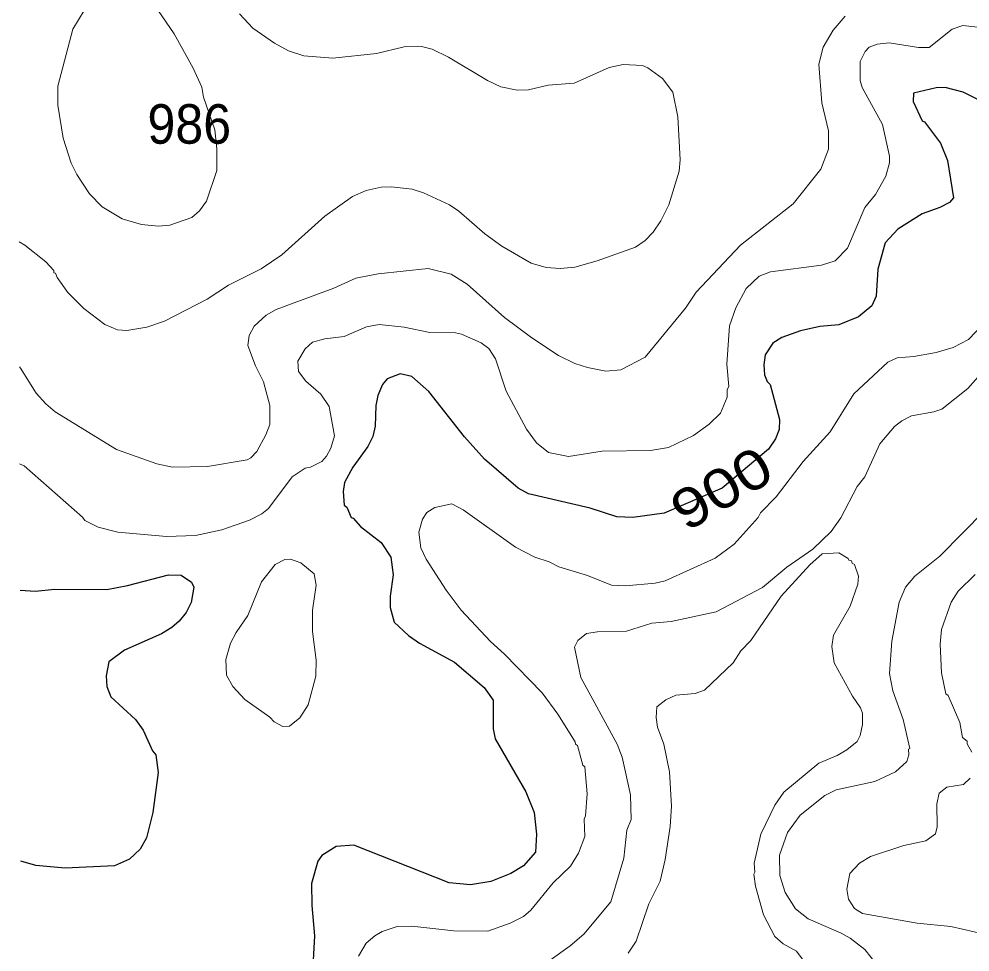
# Model space of a CAD drawing. Extents: x 447.8 to 473.9, y 7733.1 to 7760.8.
# Drawn here: x 447.836 to 449.762, y 7740.259 to 7742.149 of the extents above; entities that cross this region are included whole.
import ezdxf
from ezdxf.enums import TextEntityAlignment as Align

# ---------------------------------------------------------------- set-up
doc = ezdxf.new("R2010")
doc.units = 0
doc.header["$LTSCALE"] = 0.032
doc.layers.add('1', color=7, linetype='Continuous', lineweight=25)
doc.layers.add('2', color=7, linetype='Continuous', lineweight=13)
doc.layers.add('21', color=7, linetype='Continuous')
doc.layers.add('61', color=7, linetype='Continuous')

msp = doc.modelspace()

# ---------------------------------------------------------------- linework, layer by layer
at = {"layer": '1'}
for points in [[(449.7846, 7741.9822), (449.748, 7742.0006), (449.7116, 7742.0101), (449.6935, 7742.0093), (449.6478, 7741.9983), (449.6471, 7741.9817), (449.6649, 7741.9422), (449.6696, 7741.9401), (449.7019, 7741.8969), (449.7162, 7741.8619), (449.7287, 7741.7866), (449.7201, 7741.7772), (449.7008, 7741.7668), (449.6651, 7741.7538), (449.6156, 7741.7229), (449.5901, 7741.6954), (449.5753, 7741.6422), (449.5717, 7741.587), (449.5631, 7741.5673), (449.536, 7741.5454), (449.4961, 7741.5291), (449.4576, 7741.5259), (449.4187, 7741.5169), (449.3809, 7741.5035), (449.3626, 7741.4923), (449.3472, 7741.4686), (449.3442, 7741.4482), (449.3457, 7741.4277), (449.3513, 7741.4142), (449.3572, 7741.4082), (449.3761, 7741.3372), (449.3752, 7741.3172), (449.3681, 7741.2984), (449.354, 7741.2771), (449.2597, 7741.1986), (449.1422, 7741.1474), (449.079, 7741.139), (449.0463, 7741.1404), (448.9927, 7741.1581), (448.8676, 7741.1871), (448.8464, 7741.1985), (448.7784, 7741.2572), (448.7383, 7741.3025), (448.6657, 7741.3938), (448.6311, 7741.4242), (448.6079, 7741.4296), (448.5816, 7741.4199), (448.572, 7741.4086), (448.5624, 7741.3859), (448.5586, 7741.3659), (448.5569, 7741.3239), (448.552, 7741.3029), (448.5419, 7741.2826), (448.5119, 7741.2411), (448.4946, 7741.2095), (448.4921, 7741.1913), (448.4945, 7741.164), (448.4993, 7741.1601), (448.5085, 7741.1387), (448.5122, 7741.1377), (448.5276, 7741.1204), (448.5689, 7741.0883), (448.589, 7741.0586), (448.5938, 7741.0226), (448.5874, 7740.9797), (448.5874, 7740.9565), (448.5954, 7740.9269), (448.6245, 7740.8997), (448.6468, 7740.8842), (448.7179, 7740.8457), (448.7781, 7740.7949), (448.7961, 7740.7692), (448.7959, 7740.7112), (448.7999, 7740.6908), (448.8623, 7740.5835), (448.8792, 7740.5413), (448.8839, 7740.4976), (448.882, 7740.461), (448.8578, 7740.4337), (448.8319, 7740.4177), (448.7914, 7740.4014), (448.7502, 7740.395), (448.7068, 7740.3992), (448.5136, 7740.4751), (448.478, 7740.4725), (448.449, 7740.4544), (448.4412, 7740.4429), (448.4279, 7740.3973), (448.4287, 7740.3532), (448.4342, 7740.2919)], [(447.8377, 7740.9914), (447.8684, 7740.9898), (447.9084, 7740.9937), (448.0138, 7740.993), (448.0555, 7741.001), (448.1385, 7741.0225), (448.1641, 7741.0224), (448.185, 7741.0081), (448.1899, 7740.9979), (448.1842, 7740.9665), (448.1739, 7740.9468), (448.1603, 7740.9291), (448.1452, 7740.9162), (448.124, 7740.9035), (448.0496, 7740.8702), (448.0177, 7740.8463), (448.0119, 7740.8182), (448.0134, 7740.7969), (448.0215, 7740.776), (448.0717, 7740.7295), (448.0874, 7740.708), (448.1059, 7740.6665), (448.1124, 7740.6581), (448.1175, 7740.6226), (448.1067, 7740.5416), (448.0937, 7740.4898), (448.0813, 7740.467), (448.0596, 7740.4469), (448.0287, 7740.4335), (447.929, 7740.4288), (447.8695, 7740.4342), (447.8393, 7740.4426)], [(448.4342, 7740.2919), (448.4294, 7740.2049), (448.407, 7740.1153), (448.3948, 7740.0924), (448.3799, 7740.0722), (448.346, 7740.0451)]]:
    msp.add_lwpolyline(points, dxfattribs=at)
at = {"layer": '2'}
for points in [[(447.8356, 7741.6971), (447.8473, 7741.6907), (447.8898, 7741.6568), (447.9058, 7741.6392), (447.9063, 7741.6343), (447.9097, 7741.6335), (447.9128, 7741.625), (447.9346, 7741.5949), (447.9666, 7741.5619), (448.0097, 7741.5298), (448.0348, 7741.5188), (448.0538, 7741.518), (448.0942, 7741.5245), (448.1305, 7741.5364), (448.2167, 7741.5811), (448.2597, 7741.6098), (448.326, 7741.6429), (448.368, 7741.6712), (448.4551, 7741.7494), (448.5111, 7741.7891), (448.5386, 7741.801), (448.5694, 7741.8081), (448.5897, 7741.8089), (448.6319, 7741.8042), (448.655, 7741.7968), (448.7076, 7741.772), (448.7266, 7741.7594), (448.7792, 7741.7134), (448.8135, 7741.6882), (448.8727, 7741.6543), (448.9032, 7741.6451), (448.9315, 7741.6431), (448.9614, 7741.646), (449.0068, 7741.6588), (449.0846, 7741.6865), (449.1042, 7741.6997), (449.1202, 7741.7165), (449.1358, 7741.7395), (449.1516, 7741.7725), (449.1725, 7741.8402), (449.1748, 7741.8633), (449.1702, 7741.9502), (449.1597, 7742.0005), (449.1391, 7742.0282), (449.1094, 7742.0496), (449.0985, 7742.0543), (449.0597, 7742.0565), (449.0312, 7742.0501), (448.9598, 7742.0187), (448.9072, 7742.0149), (448.8676, 7742.0053), (448.8448, 7742.0046), (448.8115, 7742.0111), (448.7844, 7742.0241), (448.7054, 7742.0714), (448.6726, 7742.0877), (448.6506, 7742.0926), (448.6159, 7742.0919), (448.5598, 7742.079), (448.4715, 7742.0695), (448.4123, 7742.0743), (448.3815, 7742.0841), (448.3531, 7742.0993), (448.3095, 7742.13), (448.2821, 7742.1592)], [(449.5092, 7742.1544), (449.4845, 7742.1258), (449.4642, 7742.0916), (449.4556, 7742.0574), (449.4618, 7741.9791), (449.4755, 7741.9219), (449.4756, 7741.8849), (449.46, 7741.8445), (449.404, 7741.7742), (449.2971, 7741.6907), (449.2075, 7741.5955), (449.1859, 7741.5626), (449.104, 7741.4638), (449.0545, 7741.4381), (449.0244, 7741.4355), (448.9869, 7741.4426), (448.9615, 7741.4509), (448.9286, 7741.4668), (448.8746, 7741.5026), (448.819, 7741.5441), (448.7435, 7741.6113), (448.7108, 7741.6318), (448.6647, 7741.643), (448.563, 7741.6326), (448.5177, 7741.6236), (448.4732, 7741.6036), (448.3563, 7741.5603), (448.3364, 7741.5485), (448.3122, 7741.5265), (448.3015, 7741.5074), (448.299, 7741.4876), (448.3147, 7741.4461), (448.3307, 7741.414), (448.3437, 7741.3656), (448.3437, 7741.3276), (448.3356, 7741.3061), (448.3172, 7741.2727), (448.3052, 7741.2599), (448.2977, 7741.2558), (448.2177, 7741.2423), (448.1462, 7741.2407), (448.1146, 7741.2474), (448.0332, 7741.2763), (447.909, 7741.353), (447.8899, 7741.3689), (447.8704, 7741.3907), (447.8383, 7741.4416), (447.8363, 7741.4441)], [(448.1176, 7742.1656), (448.1501, 7742.1185), (448.1881, 7742.0489), (448.2056, 7742.0108), (448.2091, 7741.9906), (448.2322, 7741.9242), (448.2363, 7741.8854), (448.2364, 7741.842), (448.2157, 7741.7798), (448.2014, 7741.7603), (448.1858, 7741.7465), (448.1408, 7741.7313), (448.1184, 7741.7287), (448.0835, 7741.7325), (448.0446, 7741.7438), (448.0037, 7741.7681), (447.9784, 7741.7946), (447.9527, 7741.8336), (447.9415, 7741.8563), (447.9253, 7741.9072), (447.9141, 7741.9742), (447.9141, 7742.0128), (447.9449, 7742.1281), (447.9673, 7742.1658)], [(447.8369, 7741.2478), (447.8458, 7741.2437), (447.9645, 7741.1398), (447.969, 7741.1331), (447.9962, 7741.1192), (448.0356, 7741.1091), (448.1345, 7741.1004), (448.193, 7741.1025), (448.2465, 7741.1141), (448.3022, 7741.1336), (448.3274, 7741.1461), (448.3407, 7741.157), (448.3892, 7741.2216), (448.4155, 7741.2387), (448.4259, 7741.2409), (448.4487, 7741.2523), (448.4585, 7741.2631), (448.4671, 7741.279), (448.4748, 7741.3042), (448.4639, 7741.3635), (448.4472, 7741.3886), (448.4169, 7741.415), (448.4014, 7741.4348), (448.4001, 7741.4558), (448.4155, 7741.4807), (448.4303, 7741.4938), (448.4551, 7741.5009), (448.4943, 7741.5052), (448.5397, 7741.5254), (448.5652, 7741.5298), (448.6161, 7741.5243), (448.6675, 7741.5139), (448.7198, 7741.5129), (448.7322, 7741.5104), (448.772, 7741.493), (448.7874, 7741.4811), (448.8006, 7741.46), (448.8227, 7741.3951), (448.8638, 7741.3177), (448.8841, 7741.2902), (448.908, 7741.2705), (448.9485, 7741.2622), (449.0169, 7741.2734), (449.1145, 7741.2743), (449.1513, 7741.2807), (449.2016, 7741.3049), (449.2336, 7741.3281), (449.2563, 7741.3501), (449.27, 7741.3829), (449.2703, 7741.3981), (449.2734, 7741.4043), (449.2696, 7741.4492), (449.2751, 7741.5271), (449.2876, 7741.5637), (449.3086, 7741.6025), (449.3351, 7741.6277), (449.3578, 7741.6363), (449.4609, 7741.6502), (449.4888, 7741.6589), (449.5137, 7741.6845), (449.5487, 7741.7667), (449.5708, 7741.7928), (449.5915, 7741.8302), (449.5988, 7741.857), (449.5989, 7741.871), (449.585, 7741.935), (449.5437, 7742.01), (449.5397, 7742.0238), (449.5397, 7742.0622), (449.5494, 7742.0826), (449.5579, 7742.0912), (449.5738, 7742.0973), (449.5979, 7742.1005), (449.6573, 7742.0906), (449.6792, 7742.0911), (449.7255, 7742.1277), (449.7471, 7742.1356), (449.7839, 7742.1313)], [(449.7879, 7741.5297), (449.7592, 7741.4997), (449.7279, 7741.483), (449.6932, 7741.473), (449.6484, 7741.465), (449.6147, 7741.4625), (449.5952, 7741.4532), (449.5263, 7741.3897), (449.479, 7741.3121), (449.424, 7741.2524), (449.3694, 7741.1811), (449.3373, 7741.1481), (449.3327, 7741.1389), (449.2839, 7741.0852), (449.2457, 7741.0567), (449.1443, 7741.0108)], [(449.804, 7741.4528), (449.7575, 7741.3999), (449.7048, 7741.3585), (449.6884, 7741.3528), (449.6437, 7741.3447), (449.6236, 7741.3348), (449.6092, 7741.3229), (449.5794, 7741.2881), (449.5486, 7741.2216), (449.5332, 7741.2015), (449.5006, 7741.1383), (449.4807, 7741.1108), (449.4438, 7741.0749)], [(448.9293, 7741.0391), (448.9096, 7741.049), (448.8805, 7741.0588), (448.841, 7741.0786), (448.7355, 7741.1545), (448.7126, 7741.1667), (448.6782, 7741.1592), (448.6616, 7741.1487), (448.6532, 7741.1355), (448.6452, 7741.1094), (448.6492, 7741.0772), (448.66, 7741.0546), (448.7011, 7740.9916), (448.7312, 7740.951), (448.7905, 7740.8876), (448.819, 7740.8622), (448.8954, 7740.7835), (448.9272, 7740.7404), (448.9624, 7740.6842), (448.9629, 7740.6795), (448.9672, 7740.6768), (448.9778, 7740.6375), (448.9817, 7740.6336), (448.9866, 7740.5793), (448.9833, 7740.5345), (448.9801, 7740.5277), (448.9817, 7740.493), (448.9692, 7740.4588), (448.9527, 7740.4324), (448.9174, 7740.3987), (448.8725, 7740.3434), (448.8577, 7740.3305), (448.8304, 7740.317), (448.7855, 7740.3012), (448.7161, 7740.302), (448.6313, 7740.3115), (448.6018, 7740.3107), (448.5711, 7740.3006), (448.5563, 7740.2919), (448.5391, 7740.2769), (448.5234, 7740.2501)], [(449.5747, 7740.2317), (449.5488, 7740.2639), (449.5195, 7740.2866), (449.5009, 7740.2973), (449.4341, 7740.3259), (449.4083, 7740.3461), (449.3875, 7740.3795), (449.3769, 7740.4137), (449.3762, 7740.455), (449.3925, 7740.5006), (449.4176, 7740.5357), (449.4681, 7740.5757), (449.4906, 7740.5875), (449.5692, 7740.6044), (449.6108, 7740.6236), (449.634, 7740.6449), (449.6382, 7740.6582), (449.6376, 7740.6698), (449.6398, 7740.6711), (449.6266, 7740.7297), (449.6053, 7740.7876), (449.599, 7740.823), (449.6039, 7740.8883), (449.6185, 7740.9671), (449.6313, 7740.9976), (449.6503, 7741.0201), (449.7011, 7741.0605), (449.7919, 7741.153)], [(449.0696, 7740.2568), (449.086, 7740.281), (449.1114, 7740.3566), (449.1341, 7740.4025), (449.1444, 7740.4463), (449.1549, 7740.5131), (449.1573, 7740.5544), (449.1533, 7740.6238), (449.142, 7740.6795), (449.129, 7740.7143), (449.1261, 7740.7337), (449.1279, 7740.7551), (449.1459, 7740.7694), (449.1661, 7740.7789), (449.2053, 7740.7823), (449.2238, 7740.7894), (449.2819, 7740.8448), (449.2979, 7740.8689), (449.3178, 7740.8898), (449.3796, 7740.9796), (449.4376, 7741.0432), (449.4627, 7741.0656), (449.4961, 7741.0674), (449.5151, 7741.0558), (449.5166, 7741.0524), (449.5219, 7741.0513), (449.5235, 7741.0462), (449.5283, 7741.0439), (449.5364, 7741.0201), (449.5349, 7741.0037), (449.5191, 7740.9591), (449.4851, 7740.9004), (449.482, 7740.8776), (449.4869, 7740.8444), (449.5238, 7740.777), (449.5404, 7740.7532), (449.5442, 7740.7427), (449.5444, 7740.7196), (449.5396, 7740.6974), (449.5331, 7740.6854), (449.5127, 7740.6684), (449.4928, 7740.6569), (449.4558, 7740.6414), (449.3845, 7740.5828), (449.3666, 7740.556), (449.338, 7740.4978), (449.3249, 7740.4387), (449.3263, 7740.4208), (449.3241, 7740.4164), (449.3277, 7740.3925), (449.3438, 7740.3339), (449.3664, 7740.2903), (449.3833, 7740.2756), (449.4104, 7740.2605), (449.4322, 7740.2316)], [(449.4438, 7741.0749), (449.3911, 7741.0383), (449.3414, 7740.997), (449.2475, 7740.9478), (449.1569, 7740.9281), (449.1173, 7740.9247)], [(449.1443, 7741.0108), (449.1241, 7741.0057), (449.0641, 7741.0002), (449.0359, 7741.0018), (448.9872, 7741.0213), (448.9293, 7741.0391)], [(449.7657, 7740.6639), (449.7563, 7740.6804), (449.7559, 7740.6861), (449.7464, 7740.6935), (449.7413, 7740.7234), (449.7177, 7740.7785), (449.7129, 7740.7817), (449.7041, 7740.8242), (449.7016, 7740.8823), (449.7041, 7740.9123), (449.7239, 7740.9677), (449.7377, 7740.9895), (449.7722, 7741.0237)], [(449.1173, 7740.9247), (449.0664, 7740.9087), (449.0071, 7740.9071), (448.9848, 7740.904), (448.9678, 7740.89), (448.961, 7740.8764), (448.9735, 7740.8148), (449.0475, 7740.6795), (449.0572, 7740.6535), (449.0739, 7740.5769), (449.0754, 7740.5272), (449.0669, 7740.5054), (449.0604, 7740.449), (449.0346, 7740.3605), (448.9799, 7740.2953), (448.9519, 7740.2713), (448.8754, 7740.2164)], [(449.692, 7740.4981), (449.6951, 7740.5124), (449.6947, 7740.559), (449.6998, 7740.5804), (449.7148, 7740.5929), (449.7489, 7740.5979), (449.762, 7740.6112)], [(449.5188, 7740.4178), (449.5378, 7740.4388), (449.5602, 7740.4525), (449.6278, 7740.4743), (449.6725, 7740.484), (449.692, 7740.4981)], [(449.903, 7740.2462), (449.8247, 7740.2915), (449.794, 7740.2945), (449.7231, 7740.3106), (449.6551, 7740.3172), (449.544, 7740.337), (449.5277, 7740.347), (449.5157, 7740.3657), (449.5125, 7740.3861), (449.5188, 7740.4178)]]:
    msp.add_lwpolyline(points, dxfattribs=at)
msp.add_lwpolyline([(448.3524, 7740.7252), (448.3439, 7740.7346), (448.2929, 7740.7704), (448.269, 7740.7968), (448.2556, 7740.8193), (448.2548, 7740.8514), (448.2642, 7740.8844), (448.2757, 7740.9061), (448.2993, 7740.9402), (448.327, 7741.0084), (448.3547, 7741.044), (448.3738, 7741.0537), (448.3856, 7741.0545), (448.4062, 7741.0474), (448.4333, 7741.0251), (448.4376, 7741.0019), (448.4303, 7740.9511), (448.4302, 7740.9081), (448.4375, 7740.8498), (448.4367, 7740.8173), (448.4213, 7740.7594), (448.4043, 7740.7329), (448.3836, 7740.7162), (448.3699, 7740.7157)], close=True, dxfattribs=at)

# ---------------------------------------------------------------- texts
at = {"layer": '21', "width": 0.95}
msp.add_text('986', height=0.08, dxfattribs=at).set_placement((448.0957, 7741.896))
at = {"layer": '61', "width": 1.2}
msp.add_text('900', height=0.08, rotation=30.964, dxfattribs=at).set_placement((449.2791, 7741.1636), align=Align.CENTER)

doc.saveas('drawing.dxf')
